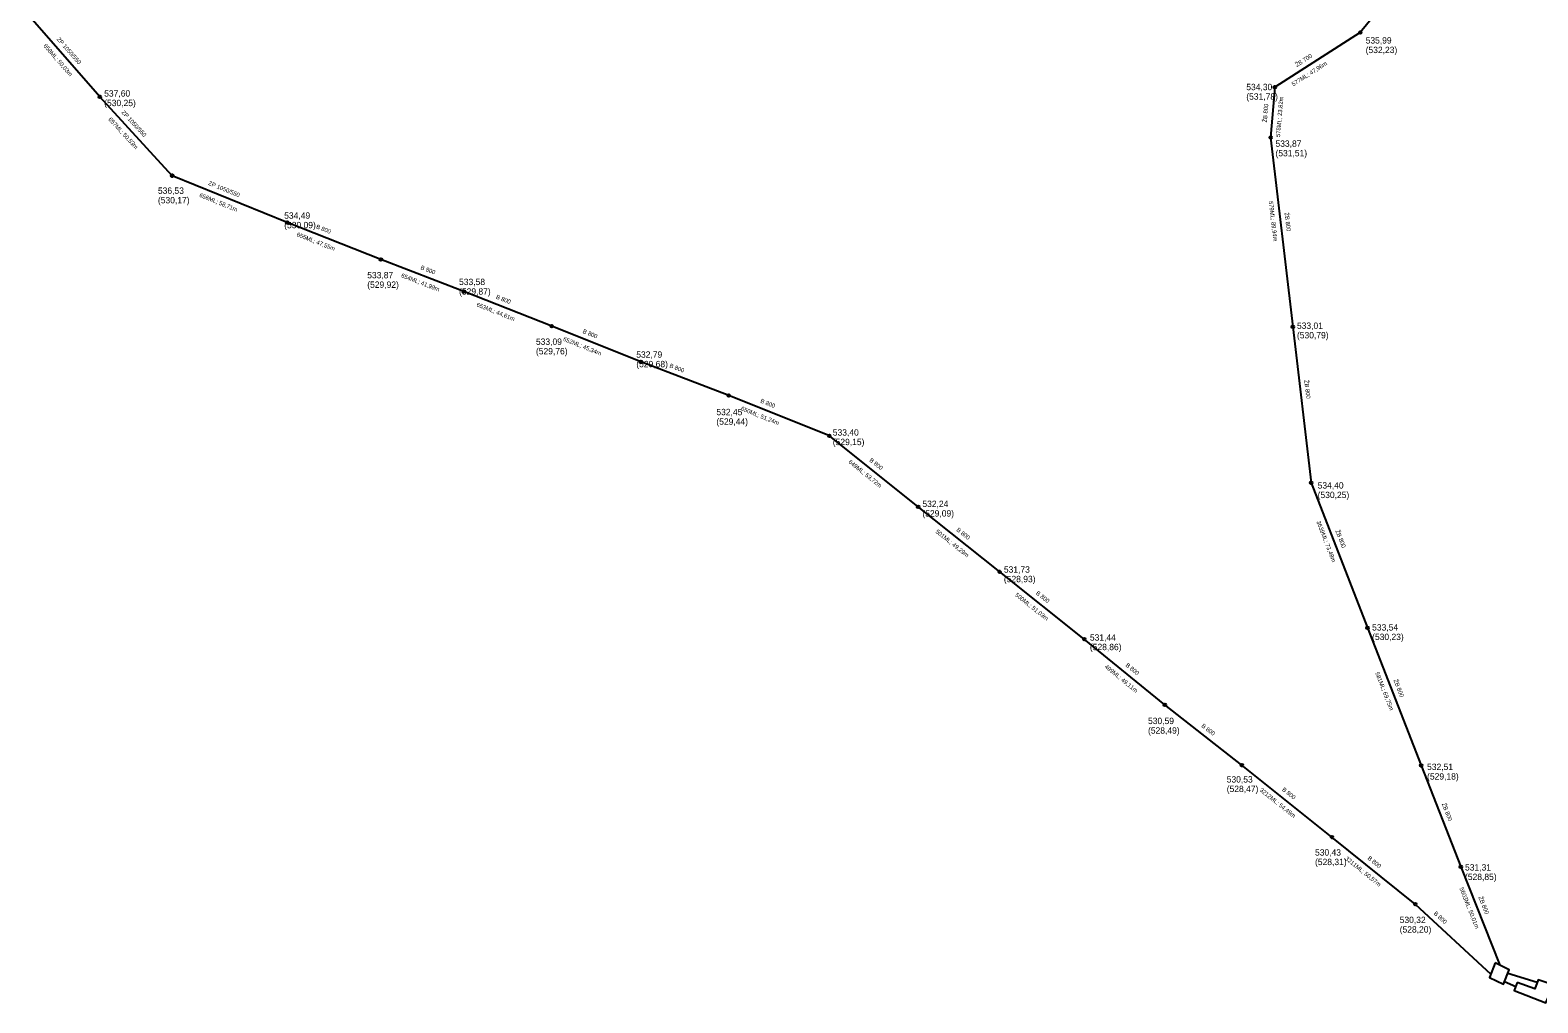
# Model space of a CAD drawing. Extents: x -867696 to -865033, y -1042522 to -1039817.
# Drawn here: x -866641 to -865929, y -1041644 to -1041185 of the extents above; entities that cross this region are included whole.
import ezdxf

# ---------------------------------------------------------------- set-up
doc = ezdxf.new("R2010")
doc.units = 0
for name, color, linetype in [('KN - jednotna', 7, 'Continuous'), ('KN - popis material', 7, 'Continuous'), ('KN - popis ostatni', 7, 'Continuous'), ('KN - popis usek delka', 7, 'Continuous'), ('KN - sachta komora', 7, 'Continuous'), ('Level 1', 7, 'Continuous')]:
    doc.layers.add(name, color=color, linetype=linetype)

# ---------------------------------------------------------------- blocks, each defined once
blk = doc.blocks.new('100.M')
at = {"layer": 'Level 1'}
blk.add_circle((0, 0), 1.27, dxfattribs=at)

msp = doc.modelspace()

# ---------------------------------------------------------------- linework, layer by layer
at = {"layer": 'KN - jednotna'}
for points in [[(-865985.758, -1041153.198), (-866012.377, -1041185.788)], [(-866607.979, -1041216.198), (-866640.847, -1041178.479)], [(-866012.377, -1041185.788), (-866052.777, -1041211.629)], [(-866052.777, -1041211.629), (-866054.756, -1041235.367)], [(-866573.737, -1041253.357), (-866607.979, -1041216.198)], [(-866054.756, -1041235.367), (-866044.27, -1041324.696)], [(-866519.359, -1041275.479), (-866573.737, -1041253.357)], [(-866475.128, -1041292.919), (-866519.359, -1041275.479)], [(-866435.939, -1041308.009), (-866475.128, -1041292.919)], [(-866394.437, -1041324.377), (-866435.939, -1041308.009)], [(-866352.367, -1041341.278), (-866394.437, -1041324.377)], [(-866044.27, -1041324.696), (-866035.628, -1041398.317)], [(-866310.815, -1041357.115), (-866352.367, -1041341.278)], [(-866263.248, -1041376.168), (-866310.815, -1041357.115)], [(-866221.297, -1041409.73), (-866263.248, -1041376.168)], [(-866035.628, -1041398.317), (-866009.008, -1041466.819)], [(-866182.777, -1041440.478), (-866221.297, -1041409.73)], [(-866142.787, -1041472.178), (-866182.777, -1041440.478)], [(-866009.008, -1041466.819), (-865983.624, -1041531.787)], [(-866104.718, -1041503.198), (-866142.787, -1041472.178)], [(-866068.349, -1041531.629), (-866104.718, -1041503.198)], [(-866025.777, -1041565.638), (-866068.349, -1041531.629)], [(-865983.624, -1041531.787), (-865964.916, -1041579.667)], [(-865986.409, -1041597.379), (-866025.777, -1041565.638)], [(-865964.916, -1041579.667), (-865946.487, -1041626.162)], [(-865986.409, -1041597.379), (-865950.763, -1041630.304)], [(-865942.625, -1041629.865), (-865928.759, -1041634.222)], [(-865944.241, -1041633.851), (-865938.966, -1041636.235)]]:
    msp.add_lwpolyline(points, dxfattribs=at)
at = {"layer": 'KN - sachta komora'}
for points in [[(-865948.702, -1041625.084), (-865951.417, -1041631.96), (-865944.721, -1041635.036), (-865942.007, -1041628.341), (-865948.702, -1041625.084)], [(-865938.317, -1041634.37), (-865939.634, -1041638.155), (-865924.658, -1041643.915), (-865922.848, -1041639.636), (-865921.202, -1041635.358), (-865928.278, -1041633.054), (-865930.006, -1041637.25), (-865938.317, -1041634.37)]]:
    msp.add_lwpolyline(points, dxfattribs=at)

# ---------------------------------------------------------------- block references
for p, xscale, yscale, rotation in [((-866012.377, -1041185.788), 0.5000000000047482, 0.5000000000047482, -137.9999986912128), ((-866052.777, -1041211.629), 0.5000000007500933, 0.5000000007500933, -120.99999982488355), ((-866607.979, -1041216.198), 0.5000000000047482, 0.5000000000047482, 132.0000013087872), ((-866054.756, -1041235.367), 0.5000000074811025, 0.5000000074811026, 90.99999994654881), ((-866573.737, -1041253.357), 0.4999999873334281, 0.499999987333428, 145.99999954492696), ((-866519.359, -1041275.479), 0.5137536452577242, 0.513753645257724, 155.31089431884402), ((-866475.128, -1041292.919), 0.5137536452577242, 0.513753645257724, 155.31089431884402), ((-866435.939, -1041308.009), 0.5137536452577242, 0.513753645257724, 155.31089431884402), ((-866394.437, -1041324.377), 0.5137536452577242, 0.513753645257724, 155.31089431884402), ((-866044.27, -1041324.696), 0.500095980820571, 0.500095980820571, 97.08900113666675), ((-866352.367, -1041341.278), 0.5137536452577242, 0.513753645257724, 155.31089431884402), ((-866310.815, -1041357.115), 0.5137536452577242, 0.513753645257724, 155.31089431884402), ((-866263.248, -1041376.168), 0.4999999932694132, 0.4999999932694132, 149.99999955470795), ((-866035.628, -1041398.317), 0.5000000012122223, 0.5000000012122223, 104.00000032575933), ((-866221.297, -1041409.73), 0.5000000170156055, 0.5000000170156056, 141.99999959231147), ((-866182.777, -1041440.478), 0.5000000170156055, 0.5000000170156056, 141.99999959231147), ((-866009.008, -1041466.819), 0.5000000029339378, 0.5000000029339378, 111.99999900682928), ((-866142.787, -1041472.178), 0.5000000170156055, 0.5000000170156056, 141.99999959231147), ((-866104.718, -1041503.198), 0.5000000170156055, 0.5000000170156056, 141.99999959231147), ((-866068.349, -1041531.629), 0.5000000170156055, 0.5000000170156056, 141.99999959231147), ((-865983.624, -1041531.787), 0.5000000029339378, 0.5000000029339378, 111.99999900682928), ((-866025.777, -1041565.638), 0.5000000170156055, 0.5000000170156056, 141.99999959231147), ((-865964.916, -1041579.667), 0.5000000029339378, 0.5000000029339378, -68.00000099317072), ((-865986.409, -1041597.379), 0.5000000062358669, 0.5000000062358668, 139.99999868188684)]:
    msp.add_blockref('100.M', p, dxfattribs=dict(at, xscale=xscale, yscale=yscale, rotation=rotation))

# ---------------------------------------------------------------- texts
at = {"layer": 'KN - popis material'}
for s, height, rotation, p in [('ZP 1050/550', 1.99999, 311.07, (-866628.436, -1041189.07)), ('ŽB 700', 2, 32.6, (-866042.376, -1041202.126)), ('ŽB 800', 2, 85.23, (-866056.579, -1041228.336)), ('ZP 1050/550', 1.99999, 312.66, (-866597.861, -1041223.637)), ('ZP 1050/550', 1.99999, 337.86, (-866556.892, -1041257.618)), ('B 800', 2, 338.48, (-866505.94, -1041278.19)), ('ŽB 800', 2, 276.7, (-866048.172, -1041270.88)), ('B 800', 2, 338.94, (-866456.592, -1041297.485)), ('B 800', 2, 338.48, (-866420.956, -1041311.339)), ('B 800', 2, 338.11, (-866379.986, -1041327.596)), ('B 800', 2, 339.14, (-866338.979, -1041343.813)), ('ŽB 800', 2, 276.7, (-866038.893, -1041349.92)), ('B 800', 2, 338.17, (-866296.044, -1041360.446)), ('B 800', 2, 321.34, (-866244.564, -1041388.042)), ('B 800', 2, 321.4, (-866203.405, -1041420.941)), ('ŽB 800', 2, 291.24, (-866024.23, -1041421.022)), ('B 800', 2, 321.6, (-866165.869, -1041450.818)), ('B 800', 2, 320.83, (-866123.492, -1041484.805)), ('ŽB 800', 2, 291.34, (-865996.756, -1041491.579)), ('B 800', 2, 321.98, (-866087.653, -1041513.491)), ('B 800', 2, 321.38, (-866049.572, -1041543.558)), ('ŽB 800', 2, 291.34, (-865973.929, -1041550.003)), ('B 800', 2, 321.12, (-866009.159, -1041575.953)), ('ŽB 800', 2, 291.62, (-865956.624, -1041594.074)), ('B 800', 2, 317.27, (-865977.878, -1041601.991))]:
    msp.add_text(s, height=height, rotation=rotation, dxfattribs=at).set_placement(p)
at = {"layer": 'KN - popis ostatni'}
for s, p in [('535,99 ', (-866009.867, -1041190.978)), ('(532,23)', (-866009.867, -1041195.478)), ('537,60 ', (-866605.869, -1041216.028)), ('534,30 ', (-866066.257, -1041212.989)), ('(530,25)', (-866605.869, -1041220.528)), ('(531,78)', (-866066.257, -1041217.489)), ('533,87 ', (-866052.466, -1041239.717)), ('(531,51)', (-866052.466, -1041244.217)), ('536,53 ', (-866580.477, -1041261.937)), ('(530,17)', (-866580.477, -1041266.437)), ('534,49 ', (-866520.819, -1041273.679)), ('(530,09)', (-866520.819, -1041278.179)), ('533,87 ', (-866481.588, -1041301.819)), ('(529,92)', (-866481.588, -1041306.319)), ('533,58 ', (-866438.189, -1041305.019)), ('(529,87)', (-866438.189, -1041309.519)), ('533,01 ', (-866042.32, -1041325.696)), ('(530,79)', (-866042.32, -1041330.196)), ('533,09 ', (-866401.877, -1041333.247)), ('(529,76)', (-866401.877, -1041337.747)), ('532,79 ', (-866354.467, -1041339.308)), ('(529,68)', (-866354.467, -1041343.808)), ('532,45 ', (-866316.625, -1041366.465)), ('(529,44)', (-866316.625, -1041370.965)), ('533,40 ', (-866261.618, -1041376.088)), ('(529,15)', (-866261.618, -1041380.588)), ('534,40 ', (-866032.548, -1041401.097)), ('(530,25)', (-866032.548, -1041405.597)), ('532,24 ', (-866219.287, -1041409.81)), ('(529,09)', (-866219.287, -1041414.31)), ('531,73 ', (-866180.787, -1041440.808)), ('(528,93)', (-866180.787, -1041445.308)), ('533,54 ', (-866006.808, -1041468.129)), ('(530,23)', (-866006.808, -1041472.629)), ('531,44 ', (-866140.147, -1041472.898)), ('(528,86)', (-866140.147, -1041477.398)), ('530,59 ', (-866112.688, -1041512.308)), ('(528,49)', (-866112.688, -1041516.808)), ('532,51 ', (-865980.834, -1041533.997)), ('530,53 ', (-866075.499, -1041539.899)), ('(529,18)', (-865980.834, -1041538.497)), ('(528,47)', (-866075.499, -1041544.399)), ('530,43 ', (-866033.787, -1041574.398)), ('(528,31)', (-866033.787, -1041578.898)), ('531,31 ', (-865962.916, -1041581.447)), ('(528,85)', (-865962.916, -1041585.947)), ('530,32 ', (-865993.779, -1041606.249)), ('(528,20)', (-865993.779, -1041610.749))]:
    msp.add_text(s, height=3, dxfattribs=at).set_placement(p)
at = {"layer": 'KN - popis usek delka'}
for s, rotation, p in [('658ML; 50,03m', 311.07, (-866634.745, -1041192.18)), ('577ML; 47,96m', 32.6, (-866044.02, -1041211.25)), ('578ML; 23,82m', 85.23, (-866050.326, -1041235.18)), ('657ML; 50,53m', 312.66, (-866604.081, -1041226.92)), ('656ML; 58,71m', 337.86, (-866561.122, -1041263.239)), ('579ML; 89,94m', 276.7, (-866055.66, -1041265.416)), ('655ML; 47,55m', 338.48, (-866515.133, -1041281.875)), ('654ML; 41,99m', 338.94, (-866465.755, -1041301.243)), ('653ML; 44,61m', 338.48, (-866430.148, -1041315.024)), ('652ML; 45,34m', 338.11, (-866389.202, -1041331.221)), ('650ML; 51,24m', 338.17, (-866305.255, -1041364.081)), ('649ML; 53,72m', 321.34, (-866254.434, -1041388.854)), ('3639ML; 73,49m', 291.24, (-866033.177, -1041416.773)), ('501ML; 49,29m', 321.4, (-866213.274, -1041421.763)), ('500ML; 51,03m', 321.6, (-866175.736, -1041451.675)), ('499ML; 49,11m', 320.83, (-866133.37, -1041485.529)), ('581ML; 69,75m', 291.34, (-866005.383, -1041488.186)), ('3212ML; 54,49m', 321.38, (-866060.144, -1041543.815)), ('3211ML; 50,57m', 321.12, (-866019.733, -1041576.162)), ('5603ML; 50,01m', 291.62, (-865965.599, -1041589.885))]:
    msp.add_text(s, height=1.99999, rotation=rotation, dxfattribs=at).set_placement(p)

doc.saveas('drawing.dxf')
